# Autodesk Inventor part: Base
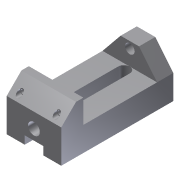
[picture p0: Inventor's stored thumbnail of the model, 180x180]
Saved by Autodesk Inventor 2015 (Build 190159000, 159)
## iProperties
Shininess: 77.0
Length Units: 11269
Angle Units: 11279
Time Units: 11290
Mass Units: 11283
Length Display Precision: 3
Angle Display Precision: 2
Created: 2002-02
Part Number: Base
Document SubType Name: Modeling
Designer: ***
Density: 1 g/cm^3
Material: Generic
Appearance: Default
Density: 0.0
Volumn: 0.0
Area: 0.0
PropertySet Name: Model Information
Control State: 0
Master: False
Checked Out: False
Author: ***
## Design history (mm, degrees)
sketch "Sketch2"
  geometry: L1 (-63.961, -4.254)-(-63.961, -37.254); L2 (-63.961, -37.254)-(88.039, -37.254); L3 (88.039, -37.254)-(88.039, 7.746); L4 (88.039, 7.746)-(68.039, 27.746); L5 (68.039, 27.746)-(58.039, 27.746); L6 (58.039, 27.746)-(58.039, -4.254); L7 (58.039, -4.254)-(-63.961, -4.254)
  constraints: 14 end point, 4 parallel, 1 perpendicular, 1 vertical
  dimensions: "d7" = 10 distance of L4.end L5.end; "d8" = 135 deg angle of L3 L4; "d9" = 33 distance of L1.start L1.end; "d10" = 152 distance of L1.end L2.end; "d11" = 65 distance between parallel lines of L5 L2; "d21" = 30 distance between parallel lines of L3 L6
extrude "Extrusion1" new body sketch "Sketch2" stored distance "d13" = 74; taper "d14" = 0 deg
sketch "Sketch3"
  geometry: L1 (0, 74)-(0, 0) reference; L2 (0, 0)-(-30, 24.5); L3 (-30, 24.5)-(-30, 49.5); L4 (-30, 49.5)-(0, 74); C1 r 6.5 at (-21, 37)
  constraints: 6 end point, 1 centre point, 1 equal length, 1 parallel
  dimensions: "d15" = 25 distance of L2.end L3.end; "d16" = 30 distance between parallel lines of L3 L1; "d17" = 13 diameter of C1; "d18" = 9 distance from line of L3 C1.centre
extrude "Extrusion2" join sketch "Sketch3" distance "d19" = 22; taper "d20" = 0 deg
sketch "Sketch4"
  geometry: L1 (0, 0)-(0, 74) reference; L2 (0, 0)-(45, 0) reference; C1 r 8 at (25, 37)
  constraints: 1 centre point
  dimensions: "d22" = 16 diameter of C1; "d23" = 25 distance from line of L1 C1.centre; "d24" = 37 distance from line of L2 C1.centre
extrude "Extrusion3" cut sketch "Sketch4" distance "d25" = 13; taper "d26" = 0 deg
sketch "Sketch5"
  geometry: L1 (45, 74)-(0, 74) reference; L2 (65, 0)-(65, 74) reference; 1 further point
  dimensions: "d27" = 12 distance from line of point (51, 62) L1; "d28" = 14 distance from line of L2 point (51, 62)
hole "Hole1" sketch "Sketch5" at (51, 62) diameter "d29" = 6; stored, may be unused: countersink angle "d33" = 82 deg, drill point angle "d35" = 0 deg; dims "d30" = 6, "d31" = 8, "d32" = 10, "d34" = 30
mirror "Mirror1"
sketch "Sketch6"
  geometry: L1 (100, 0)-(100, 74) reference; L2 (100, 74)-(0, 74) reference; L3 (14, 45)-(92, 45); L4 (92, 29)-(14, 29); A1 r 8 centre (92, 37) between (92, 29) and (92, 45); A2 r 8 centre (14, 37) between (14, 45) and (14, 29)
  constraints: 4 end point, 4 point on circle, 4 tangent, 2 centre point, 1 horizontal, 1 parallel
  dimensions: "d36" = 8 radius of A2; "d37" = 78 distance of L4.start L4.end; "d38" = 8 distance from line of L1 A1.centre; "d39" = 37 distance from line of L2 A2.centre
extrude "Extrusion4" cut sketch "Sketch6" stored distance "d40" = 13; taper "d41" = 0 deg
sketch "Sketch7"
  geometry: L1 (0, 49.5)-(11, 49.5); L2 (11, 49.5)-(11, 24.5); L3 (11, 24.5)-(0, 24.5); L4 (0, 24.5)-(0, 49.5); L5 (45, 74)-(0, 74) reference; L6 (0, 0)-(0, 74) reference
  constraints: 8 end point, 2 parallel, 1 collinear, 1 horizontal, 1 perpendicular
  dimensions: "d42" = 25 distance of L3.end L1.start; "d43" = 11 distance of L1.start L1.end; "d44" = 24.5 distance between parallel lines of L5 L1
extrude "Extrusion5" cut sketch "Sketch7" stored distance "d45" = 13; taper "d46" = 0 deg
body "Solid1"
